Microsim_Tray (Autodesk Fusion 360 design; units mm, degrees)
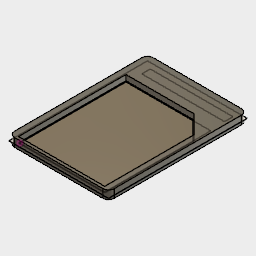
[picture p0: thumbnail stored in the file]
sketch "Sketch1" plane through (0, 0, 0) normal (0, 1, 0) x axis (1, 0, 0)
  line L1 (12, 0) -> (0, 0)
  line L2 (12, 15) -> (12, 12.5)
  line L3 (0, 15) -> (9.5, 15)
  line L4 (0, 0) -> (0, 15)
  line L5 (12, 12.5) -> (9.5, 15)
  line L6 (9.5, 15) -> (12, 15)
  line L7 (12, 12.5) -> (12, 0)
  line L8 (-1.05, -0.51) -> (-1.05, 19.1)
  line L9 (13.05, -0.51) -> (-1.05, -0.51)
  line L10 (13.05, 19.1) -> (13.05, -0.51)
  line L11 (-1.05, 19.1) -> (13.05, 19.1)
  line L12 (11.85, 18.3) -> (0.15, 18.3)
  line L13 (11.85, 17.1) -> (11.85, 18.3)
  line L14 (0.15, 17.1) -> (11.85, 17.1)
  line L15 (0.15, 18.3) -> (0.15, 17.1)
  line L16 (12.1, 12.5414) -> (9.5414, 15.1)
  line L17 (12.1, 12.5414) -> (12.1, -0.1)
  line L18 (12.1, -0.1) -> (-0.1, -0.1)
  line L19 (-0.1, -0.1) -> (-0.1, 15.1)
  line L20 (-0.1, 15.1) -> (9.5414, 15.1)
  point P2 (0, 0)
  point P3 (12, 0)
  point P5 (0, 15)
  point P4 (12, 15)
  point P6 (9.5, 15)
  point P7 (12, 12.5)
  point P17 (0.15, 18.3)
  point P20 (0.15, 17.1)
  dimension "d3" distance P2 P3 = 12
  dimension "d4" distance P2 P5 = 15
  dimension "d5" distance P4 P6 = 2.5
  dimension "d6" distance P4 P7 = 2.5
  dimension "d12" = 0.1
  dimension "d13" distance L9 L18 = 0.41
  dimension "d14" distance L8 L19 = 0.95
  dimension "d15" distance L10 L17 = 0.95
  dimension "d16" distance L11 L20 = 4
  dimension "d22" distance L8 L15 = 1.2
  dimension "d23" distance L10 L13 = 1.2
  dimension "d24" distance L11 L12 = 0.8
  dimension "d25" distance P17 P20 = 1.2
extrude "Extrude1" new body sketch "Sketch1" profile of L1 L2 L3 L4 L5 L6 L7 L8 L9 L10 L11 L16 L17 L18 L19 L20 against normal blind 0.4
extrude "Extrude2" sketch "Sketch1" profile of L2 L6 L8 L9 L10 L11 L16 L17 L18 L19 L20 blind 0.8
fillet "Fillet1" radius 0.8
extrude "Extrude3" sketch "Sketch1" profile of L12 L13 L14 L15 to an object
